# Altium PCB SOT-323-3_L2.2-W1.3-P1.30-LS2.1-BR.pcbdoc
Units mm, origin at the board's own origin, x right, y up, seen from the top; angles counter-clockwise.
Board outline 15.79 x 15.35 mm, 2 copper layers (Top Layer, Bottom Layer), stack 0 mm thick; 1 components, 0 nets, 3 pads, 0 vias.
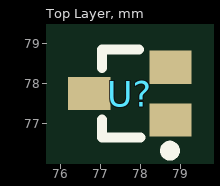
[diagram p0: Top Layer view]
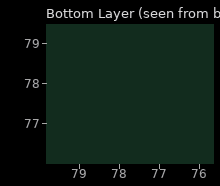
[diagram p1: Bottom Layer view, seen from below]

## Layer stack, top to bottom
Top Layer: signal copper (thickness not stored)
Bottom Layer: signal copper (thickness not stored)

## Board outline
85.636,69.85 69.85,69.85 69.85,85.199 85.636,85.199

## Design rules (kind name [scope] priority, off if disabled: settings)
PasteMaskExpansion "Paste Mask Expansion" [All] p1: expansion=0
SolderMaskExpansion "Solder Mask Expansion" [IsVia] p1: expansion=-25.4 istentingtop=TRUE
SolderMaskExpansion "Solder Mask Expansion" [All] p2: expansion=0.051 istentingtop=FALSE

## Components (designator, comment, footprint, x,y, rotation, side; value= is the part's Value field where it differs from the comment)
U? "" SOT-323-3_L2.2-W1.3-P1.30-LS2.1-BR 77.743,77.749 r0 top

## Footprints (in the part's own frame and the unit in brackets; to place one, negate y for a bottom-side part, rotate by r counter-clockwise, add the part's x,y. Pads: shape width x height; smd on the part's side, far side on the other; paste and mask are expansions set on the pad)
SOT-323-3_L2.2-W1.3-P1.30-LS2.1-BR [mil]
  rect 41.5x32.52 smd: 1(40,-26) 2(40,26) 3(-40,0)
  silkscreen extent -28,-61 44,43

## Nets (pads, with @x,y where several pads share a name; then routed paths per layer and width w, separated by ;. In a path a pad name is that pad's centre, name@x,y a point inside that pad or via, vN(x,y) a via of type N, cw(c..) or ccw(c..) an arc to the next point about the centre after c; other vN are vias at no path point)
pads on no net: U?.1 U?.2 U?.3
